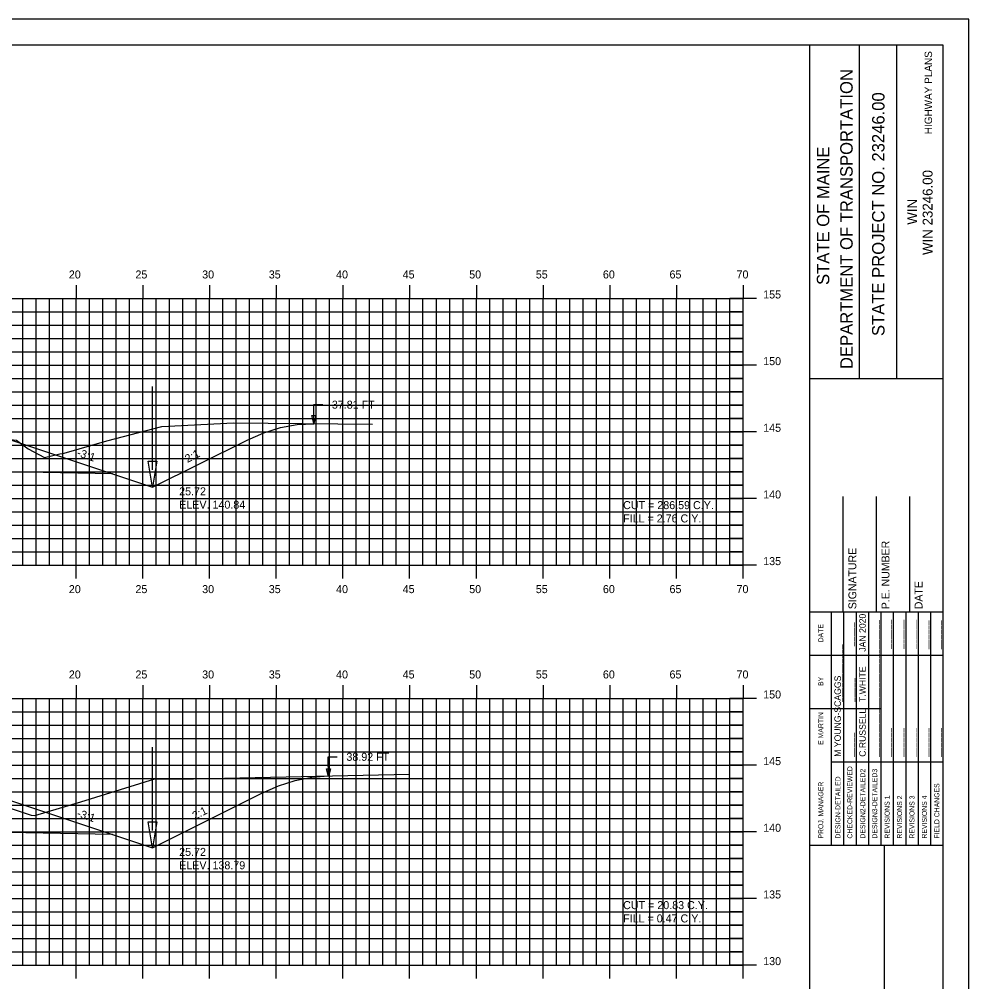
# Model space of a CAD drawing. Extents: x 1146746 to 1146916, y 608981 to 609091.
# Drawn here: x 1146845.2 to 1146916.3, y 609019.1 to 609091.3 of the extents above; entities that cross this region are included whole.
import ezdxf

# ---------------------------------------------------------------- set-up
doc = ezdxf.new("R2010")
doc.units = 0
for name, color, linetype in [('ANNOTATION', 7, 'Continuous'), ('BORDER', 7, 'Continuous'), ('D_Drainage_Ditch_Line', 7, 'Continuous'), ('D_Roadway_SlopeLines', 7, 'Continuous'), ('D_Roadway_SubGrade', 7, 'Continuous'), ('D_Text_Standard', 7, 'Continuous'), ('H_V ANNOTATION', 7, 'Continuous'), ('HIGHWAY_TITLE', 7, 'Continuous'), ('MAJOR', 7, 'Continuous'), ('MINOR', 7, 'Continuous'), ('PLOT BOUNDARY', 7, 'Continuous'), ('S_Roadway_Centerline', 7, 'Continuous')]:
    doc.layers.add(name, color=color, linetype=linetype)

msp = doc.modelspace()

# ---------------------------------------------------------------- linework, layer by layer
for points in [[(1146791.047, 609061.273), (1146792.297, 609061.185), (1146793.547, 609060.943), (1146794.797, 609060.547), (1146796.047, 609059.999), (1146803.703, 609056.171), (1146806.703, 609057.171), (1146814.427, 609059.745), (1146814.428, 609059.745), (1146818.428, 609059.905), (1146829.428, 609060.125), (1146840.428, 609059.905), (1146844.428, 609059.745), (1146852.151, 609057.171), (1146855.151, 609056.171), (1146862.242, 609059.716), (1146863.492, 609060.262), (1146864.742, 609060.648), (1146865.992, 609060.875), (1146867.242, 609060.943)], [(1146800.428, 609033.54), (1146814.428, 609032.7), (1146818.428, 609032.86), (1146829.428, 609033.08), (1146840.428, 609032.86), (1146844.428, 609032.7), (1146852.151, 609030.126), (1146855.151, 609029.126), (1146863.344, 609033.222), (1146864.594, 609033.772), (1146865.844, 609034.173), (1146867.094, 609034.424), (1146868.344, 609034.526)]]:
    msp.add_lwpolyline(points)
at = {"layer": 'BORDER'}
for p, q in [((1146904.428, 608984.335), (1146904.428, 609089.335)), ((1146908.157, 609064.332), (1146908.157, 609089.332)), ((1146910.952, 609064.332), (1146910.952, 609089.332)), ((1146904.429, 609064.329), (1146914.428, 609064.329)), ((1146906.928, 609046.838), (1146906.928, 609055.485)), ((1146909.428, 609046.838), (1146909.428, 609055.485)), ((1146911.928, 609046.838), (1146911.928, 609055.485)), ((1146904.428, 609046.838), (1146914.428, 609046.838)), ((1146904.428, 609029.338), (1146914.428, 609029.338)), ((1146910.019, 608994.338), (1146910.019, 609029.338))]:
    msp.add_line(p, q, dxfattribs=at)
msp.add_lwpolyline([(1146754.428, 608984.335), (1146914.428, 608984.335), (1146914.428, 609089.335), (1146754.428, 609089.335)], close=True, dxfattribs=at)
for points in [[(1146906.043, 609043.588), (1146906.043, 609046.838)], [(1146906.975, 609029.341), (1146906.975, 609046.838)], [(1146907.907, 609046.838), (1146907.907, 609029.341)], [(1146908.839, 609029.341), (1146908.839, 609046.838)], [(1146909.771, 609029.341), (1146909.771, 609046.838)], [(1146910.702, 609029.341), (1146910.702, 609046.838)], [(1146911.634, 609029.341), (1146911.634, 609046.838)], [(1146912.566, 609029.341), (1146912.566, 609046.838)], [(1146913.497, 609029.341), (1146913.497, 609046.838)], [(1146906.044, 609029.341), (1146906.044, 609046.132)], [(1146904.428, 609043.588), (1146914.428, 609043.588)], [(1146904.428, 609039.588), (1146906.044, 609039.588)], [(1146906.043, 609039.588), (1146909.77, 609039.588)], [(1146906.043, 609035.588), (1146914.428, 609035.588)]]:
    msp.add_lwpolyline(points, dxfattribs=at)
at = {"layer": 'D_Drainage_Ditch_Line'}
for p, q in [((1146855.151, 609057.483), (1146855.152, 609063.727)), ((1146855.151, 609030.438), (1146855.152, 609036.681))]:
    msp.add_line(p, q, dxfattribs=at)
for points in [[(1146854.823, 609058.139), (1146855.479, 609058.139), (1146855.151, 609056.171)], [(1146854.823, 609031.094), (1146855.479, 609031.094), (1146855.151, 609029.126)]]:
    msp.add_lwpolyline(points, close=True, dxfattribs=at)
at = {"layer": 'D_Roadway_SlopeLines'}
for points in [[(1146855.151, 609056.171), (1146862.242, 609059.716), (1146863.492, 609060.262), (1146864.742, 609060.648), (1146865.992, 609060.875), (1146867.242, 609060.943)], [(1146852.151, 609057.171), (1146855.151, 609056.171)], [(1146855.151, 609029.126), (1146863.344, 609033.222), (1146864.594, 609033.772), (1146865.844, 609034.173), (1146867.094, 609034.424), (1146868.344, 609034.526)], [(1146852.151, 609030.126), (1146855.151, 609029.126)]]:
    msp.add_lwpolyline(points, dxfattribs=at)
at = {"layer": 'D_Roadway_SubGrade'}
for points in [[(1146840.428, 609059.489), (1146840.428, 609059.655), (1146844.428, 609059.495), (1146844.428, 609059.745), (1146844.428, 609059.745), (1146852.151, 609057.171), (1146840.428, 609057.405)], [(1146840.428, 609032.443), (1146840.428, 609032.61), (1146844.428, 609032.45), (1146844.428, 609032.7), (1146844.428, 609032.7), (1146852.151, 609030.126), (1146840.428, 609030.36)]]:
    msp.add_lwpolyline(points, close=True, dxfattribs=at)
at = {"layer": 'D_Text_Standard'}
for points in [[(1146867.242, 609060.966), (1146867.238, 609062.37), (1146867.918, 609062.37)], [(1146868.344, 609034.472), (1146868.327, 609035.958), (1146869.007, 609035.958)]]:
    msp.add_lwpolyline(points, dxfattribs=at)
for points in [[(1146867.242, 609060.966), (1146867.095, 609061.548), (1146867.386, 609061.549)], [(1146868.344, 609034.472), (1146868.192, 609035.053), (1146868.483, 609035.056)]]:
    msp.add_lwpolyline(points, close=True, dxfattribs=at)
at = {"layer": 'MAJOR'}
for p, q in [((1146849.428, 609071.337), (1146849.428, 609070.335)), ((1146854.428, 609071.337), (1146854.428, 609070.335)), ((1146859.428, 609071.337), (1146859.428, 609070.335)), ((1146864.428, 609071.337), (1146864.428, 609070.335)), ((1146869.428, 609071.337), (1146869.428, 609070.335)), ((1146874.428, 609071.337), (1146874.428, 609070.335)), ((1146879.428, 609071.337), (1146879.428, 609070.335)), ((1146884.428, 609071.337), (1146884.428, 609070.335)), ((1146889.428, 609071.337), (1146889.428, 609070.335)), ((1146894.428, 609071.337), (1146894.428, 609070.335)), ((1146899.428, 609071.337), (1146899.428, 609070.335)), ((1146759.428, 609070.335), (1146899.428, 609070.335)), ((1146759.428, 609070.335), (1146899.428, 609070.335)), ((1146849.428, 609050.335), (1146849.428, 609070.335)), ((1146854.428, 609050.335), (1146854.428, 609070.335)), ((1146859.428, 609050.335), (1146859.428, 609070.335)), ((1146864.428, 609050.335), (1146864.428, 609070.335)), ((1146869.428, 609050.335), (1146869.428, 609070.335)), ((1146874.428, 609050.335), (1146874.428, 609070.335)), ((1146879.428, 609050.335), (1146879.428, 609070.335)), ((1146884.428, 609050.335), (1146884.428, 609070.335)), ((1146889.428, 609050.335), (1146889.428, 609070.335)), ((1146894.428, 609050.335), (1146894.428, 609070.335)), ((1146900.43, 609070.335), (1146898.426, 609070.335)), ((1146899.428, 609050.335), (1146899.428, 609070.335)), ((1146899.428, 609050.335), (1146899.428, 609070.335)), ((1146759.428, 609065.335), (1146899.428, 609065.335)), ((1146900.43, 609065.335), (1146898.426, 609065.335)), ((1146759.428, 609060.335), (1146899.428, 609060.335)), ((1146900.43, 609060.335), (1146898.426, 609060.335)), ((1146759.428, 609055.335), (1146899.428, 609055.335)), ((1146900.43, 609055.335), (1146898.426, 609055.335)), ((1146759.428, 609050.335), (1146899.428, 609050.335)), ((1146759.428, 609050.335), (1146899.428, 609050.335)), ((1146849.428, 609049.333), (1146849.428, 609050.335)), ((1146854.428, 609049.333), (1146854.428, 609050.335)), ((1146859.428, 609049.333), (1146859.428, 609050.335)), ((1146864.428, 609049.333), (1146864.428, 609050.335)), ((1146869.428, 609049.333), (1146869.428, 609050.335)), ((1146874.428, 609049.333), (1146874.428, 609050.335)), ((1146879.428, 609049.333), (1146879.428, 609050.335)), ((1146884.428, 609049.333), (1146884.428, 609050.335)), ((1146889.428, 609049.333), (1146889.428, 609050.335)), ((1146894.428, 609049.333), (1146894.428, 609050.335)), ((1146900.43, 609050.335), (1146898.426, 609050.335)), ((1146899.428, 609049.333), (1146899.428, 609050.335)), ((1146849.428, 609041.337), (1146849.428, 609040.335)), ((1146854.428, 609041.337), (1146854.428, 609040.335)), ((1146859.428, 609041.337), (1146859.428, 609040.335)), ((1146864.428, 609041.337), (1146864.428, 609040.335)), ((1146869.428, 609041.337), (1146869.428, 609040.335)), ((1146874.428, 609041.337), (1146874.428, 609040.335)), ((1146879.428, 609041.337), (1146879.428, 609040.335)), ((1146884.428, 609041.337), (1146884.428, 609040.335)), ((1146889.428, 609041.337), (1146889.428, 609040.335)), ((1146894.428, 609041.337), (1146894.428, 609040.335)), ((1146899.428, 609041.337), (1146899.428, 609040.335)), ((1146759.428, 609040.335), (1146899.428, 609040.335)), ((1146759.428, 609040.335), (1146899.428, 609040.335)), ((1146849.428, 609020.335), (1146849.428, 609040.335)), ((1146854.428, 609020.335), (1146854.428, 609040.335)), ((1146859.428, 609020.335), (1146859.428, 609040.335)), ((1146864.428, 609020.335), (1146864.428, 609040.335)), ((1146869.428, 609020.335), (1146869.428, 609040.335)), ((1146874.428, 609020.335), (1146874.428, 609040.335)), ((1146879.428, 609020.335), (1146879.428, 609040.335)), ((1146884.428, 609020.335), (1146884.428, 609040.335)), ((1146889.428, 609020.335), (1146889.428, 609040.335)), ((1146894.428, 609020.335), (1146894.428, 609040.335)), ((1146900.43, 609040.335), (1146898.426, 609040.335)), ((1146899.428, 609020.335), (1146899.428, 609040.335)), ((1146899.428, 609020.335), (1146899.428, 609040.335)), ((1146759.428, 609035.335), (1146899.428, 609035.335)), ((1146900.43, 609035.335), (1146898.426, 609035.335)), ((1146759.428, 609030.335), (1146899.428, 609030.335)), ((1146900.43, 609030.335), (1146898.426, 609030.335)), ((1146759.428, 609025.335), (1146899.428, 609025.335)), ((1146900.43, 609025.335), (1146898.426, 609025.335)), ((1146759.428, 609020.335), (1146899.428, 609020.335)), ((1146759.428, 609020.335), (1146899.428, 609020.335)), ((1146849.428, 609019.333), (1146849.428, 609020.335)), ((1146854.428, 609019.333), (1146854.428, 609020.335)), ((1146859.428, 609019.333), (1146859.428, 609020.335)), ((1146864.428, 609019.333), (1146864.428, 609020.335)), ((1146869.428, 609019.333), (1146869.428, 609020.335)), ((1146874.428, 609019.333), (1146874.428, 609020.335)), ((1146879.428, 609019.333), (1146879.428, 609020.335)), ((1146884.428, 609019.333), (1146884.428, 609020.335)), ((1146889.428, 609019.333), (1146889.428, 609020.335)), ((1146894.428, 609019.333), (1146894.428, 609020.335)), ((1146900.43, 609020.335), (1146898.426, 609020.335)), ((1146899.428, 609019.333), (1146899.428, 609020.335))]:
    msp.add_line(p, q, dxfattribs=at)
at = {"layer": 'MINOR'}
for p, q in [((1146845.428, 609050.335), (1146845.428, 609070.335)), ((1146846.428, 609050.335), (1146846.428, 609070.335)), ((1146847.428, 609050.335), (1146847.428, 609070.335)), ((1146848.428, 609050.335), (1146848.428, 609070.335)), ((1146850.428, 609050.335), (1146850.428, 609070.335)), ((1146851.428, 609050.335), (1146851.428, 609070.335)), ((1146852.428, 609050.335), (1146852.428, 609070.335)), ((1146853.428, 609050.335), (1146853.428, 609070.335)), ((1146855.428, 609050.335), (1146855.428, 609070.335)), ((1146856.428, 609050.335), (1146856.428, 609070.335)), ((1146857.428, 609050.335), (1146857.428, 609070.335)), ((1146858.428, 609050.335), (1146858.428, 609070.335)), ((1146860.428, 609050.335), (1146860.428, 609070.335)), ((1146861.428, 609050.335), (1146861.428, 609070.335)), ((1146862.428, 609050.335), (1146862.428, 609070.335)), ((1146863.428, 609050.335), (1146863.428, 609070.335)), ((1146865.428, 609050.335), (1146865.428, 609070.335)), ((1146866.428, 609050.335), (1146866.428, 609070.335)), ((1146867.428, 609050.335), (1146867.428, 609070.335)), ((1146868.428, 609050.335), (1146868.428, 609070.335)), ((1146870.428, 609050.335), (1146870.428, 609070.335)), ((1146871.428, 609050.335), (1146871.428, 609070.335)), ((1146872.428, 609050.335), (1146872.428, 609070.335)), ((1146873.428, 609050.335), (1146873.428, 609070.335)), ((1146875.428, 609050.335), (1146875.428, 609070.335)), ((1146876.428, 609050.335), (1146876.428, 609070.335)), ((1146877.428, 609050.335), (1146877.428, 609070.335)), ((1146878.428, 609050.335), (1146878.428, 609070.335)), ((1146880.428, 609050.335), (1146880.428, 609070.335)), ((1146881.428, 609050.335), (1146881.428, 609070.335)), ((1146882.428, 609050.335), (1146882.428, 609070.335)), ((1146883.428, 609050.335), (1146883.428, 609070.335)), ((1146885.428, 609050.335), (1146885.428, 609070.335)), ((1146886.428, 609050.335), (1146886.428, 609070.335)), ((1146887.428, 609050.335), (1146887.428, 609070.335)), ((1146888.428, 609050.335), (1146888.428, 609070.335)), ((1146890.428, 609050.335), (1146890.428, 609070.335)), ((1146891.428, 609050.335), (1146891.428, 609070.335)), ((1146892.428, 609050.335), (1146892.428, 609070.335)), ((1146893.428, 609050.335), (1146893.428, 609070.335)), ((1146895.428, 609050.335), (1146895.428, 609070.335)), ((1146896.428, 609050.335), (1146896.428, 609070.335)), ((1146897.428, 609050.335), (1146897.428, 609070.335)), ((1146898.428, 609050.335), (1146898.428, 609070.335)), ((1146759.428, 609069.335), (1146899.428, 609069.335)), ((1146899.428, 609069.335), (1146898.426, 609069.335)), ((1146759.428, 609068.335), (1146899.428, 609068.335)), ((1146899.428, 609068.335), (1146898.426, 609068.335)), ((1146759.428, 609067.335), (1146899.428, 609067.335)), ((1146899.428, 609067.335), (1146898.426, 609067.335)), ((1146759.428, 609066.335), (1146899.428, 609066.335)), ((1146899.428, 609066.335), (1146898.426, 609066.335)), ((1146759.428, 609064.335), (1146899.428, 609064.335)), ((1146899.428, 609064.335), (1146898.426, 609064.335)), ((1146759.428, 609063.335), (1146899.428, 609063.335)), ((1146899.428, 609063.335), (1146898.426, 609063.335)), ((1146759.428, 609062.335), (1146899.428, 609062.335)), ((1146899.428, 609062.335), (1146898.426, 609062.335)), ((1146759.428, 609061.335), (1146899.428, 609061.335)), ((1146899.428, 609061.335), (1146898.426, 609061.335)), ((1146759.428, 609059.335), (1146899.428, 609059.335)), ((1146899.428, 609059.335), (1146898.426, 609059.335)), ((1146759.428, 609058.335), (1146899.428, 609058.335)), ((1146899.428, 609058.335), (1146898.426, 609058.335)), ((1146759.428, 609057.335), (1146899.428, 609057.335)), ((1146899.428, 609057.335), (1146898.426, 609057.335)), ((1146759.428, 609056.335), (1146899.428, 609056.335)), ((1146899.428, 609056.335), (1146898.426, 609056.335)), ((1146759.428, 609054.335), (1146899.428, 609054.335)), ((1146899.428, 609054.335), (1146898.426, 609054.335)), ((1146759.428, 609053.335), (1146899.428, 609053.335)), ((1146899.428, 609053.335), (1146898.426, 609053.335)), ((1146759.428, 609052.335), (1146899.428, 609052.335)), ((1146899.428, 609052.335), (1146898.426, 609052.335)), ((1146759.428, 609051.335), (1146899.428, 609051.335)), ((1146899.428, 609051.335), (1146898.426, 609051.335)), ((1146845.428, 609020.335), (1146845.428, 609040.335)), ((1146846.428, 609020.335), (1146846.428, 609040.335)), ((1146847.428, 609020.335), (1146847.428, 609040.335)), ((1146848.428, 609020.335), (1146848.428, 609040.335)), ((1146850.428, 609020.335), (1146850.428, 609040.335)), ((1146851.428, 609020.335), (1146851.428, 609040.335)), ((1146852.428, 609020.335), (1146852.428, 609040.335)), ((1146853.428, 609020.335), (1146853.428, 609040.335)), ((1146855.428, 609020.335), (1146855.428, 609040.335)), ((1146856.428, 609020.335), (1146856.428, 609040.335)), ((1146857.428, 609020.335), (1146857.428, 609040.335)), ((1146858.428, 609020.335), (1146858.428, 609040.335)), ((1146860.428, 609020.335), (1146860.428, 609040.335)), ((1146861.428, 609020.335), (1146861.428, 609040.335)), ((1146862.428, 609020.335), (1146862.428, 609040.335)), ((1146863.428, 609020.335), (1146863.428, 609040.335)), ((1146865.428, 609020.335), (1146865.428, 609040.335)), ((1146866.428, 609020.335), (1146866.428, 609040.335)), ((1146867.428, 609020.335), (1146867.428, 609040.335)), ((1146868.428, 609020.335), (1146868.428, 609040.335)), ((1146870.428, 609020.335), (1146870.428, 609040.335)), ((1146871.428, 609020.335), (1146871.428, 609040.335)), ((1146872.428, 609020.335), (1146872.428, 609040.335)), ((1146873.428, 609020.335), (1146873.428, 609040.335)), ((1146875.428, 609020.335), (1146875.428, 609040.335)), ((1146876.428, 609020.335), (1146876.428, 609040.335)), ((1146877.428, 609020.335), (1146877.428, 609040.335)), ((1146878.428, 609020.335), (1146878.428, 609040.335)), ((1146880.428, 609020.335), (1146880.428, 609040.335)), ((1146881.428, 609020.335), (1146881.428, 609040.335)), ((1146882.428, 609020.335), (1146882.428, 609040.335)), ((1146883.428, 609020.335), (1146883.428, 609040.335)), ((1146885.428, 609020.335), (1146885.428, 609040.335)), ((1146886.428, 609020.335), (1146886.428, 609040.335)), ((1146887.428, 609020.335), (1146887.428, 609040.335)), ((1146888.428, 609020.335), (1146888.428, 609040.335)), ((1146890.428, 609020.335), (1146890.428, 609040.335)), ((1146891.428, 609020.335), (1146891.428, 609040.335)), ((1146892.428, 609020.335), (1146892.428, 609040.335)), ((1146893.428, 609020.335), (1146893.428, 609040.335)), ((1146895.428, 609020.335), (1146895.428, 609040.335)), ((1146896.428, 609020.335), (1146896.428, 609040.335)), ((1146897.428, 609020.335), (1146897.428, 609040.335)), ((1146898.428, 609020.335), (1146898.428, 609040.335)), ((1146759.428, 609039.335), (1146899.428, 609039.335)), ((1146899.428, 609039.335), (1146898.426, 609039.335)), ((1146759.428, 609038.335), (1146899.428, 609038.335)), ((1146899.428, 609038.335), (1146898.426, 609038.335)), ((1146759.428, 609037.335), (1146899.428, 609037.335)), ((1146899.428, 609037.335), (1146898.426, 609037.335)), ((1146759.428, 609036.335), (1146899.428, 609036.335)), ((1146899.428, 609036.335), (1146898.426, 609036.335)), ((1146759.428, 609034.335), (1146899.428, 609034.335)), ((1146899.428, 609034.335), (1146898.426, 609034.335)), ((1146759.428, 609033.335), (1146899.428, 609033.335)), ((1146899.428, 609033.335), (1146898.426, 609033.335)), ((1146759.428, 609032.335), (1146899.428, 609032.335)), ((1146899.428, 609032.335), (1146898.426, 609032.335)), ((1146759.428, 609031.335), (1146899.428, 609031.335)), ((1146899.428, 609031.335), (1146898.426, 609031.335)), ((1146759.428, 609029.335), (1146899.428, 609029.335)), ((1146899.428, 609029.335), (1146898.426, 609029.335)), ((1146759.428, 609028.335), (1146899.428, 609028.335)), ((1146899.428, 609028.335), (1146898.426, 609028.335)), ((1146759.428, 609027.335), (1146899.428, 609027.335)), ((1146899.428, 609027.335), (1146898.426, 609027.335)), ((1146759.428, 609026.335), (1146899.428, 609026.335)), ((1146899.428, 609026.335), (1146898.426, 609026.335)), ((1146759.428, 609024.335), (1146899.428, 609024.335)), ((1146899.428, 609024.335), (1146898.426, 609024.335)), ((1146759.428, 609023.335), (1146899.428, 609023.335)), ((1146899.428, 609023.335), (1146898.426, 609023.335)), ((1146759.428, 609022.335), (1146899.428, 609022.335)), ((1146899.428, 609022.335), (1146898.426, 609022.335)), ((1146759.428, 609021.335), (1146899.428, 609021.335)), ((1146899.428, 609021.335), (1146898.426, 609021.335))]:
    msp.add_line(p, q, dxfattribs=at)
at = {"layer": 'PLOT BOUNDARY'}
msp.add_lwpolyline([(1146746.335, 608981.276), (1146916.335, 608981.276), (1146916.335, 609091.276), (1146746.335, 609091.276)], close=True, dxfattribs=at)
at = {"layer": 'S_Roadway_Centerline'}
for points in [[(1146779.336, 609061.362), (1146783.547, 609061.347), (1146805.256, 609061.134), (1146809.082, 609059.861), (1146811.069, 609059.254), (1146812.495, 609059.513), (1146815.447, 609060.131), (1146817.252, 609060.222), (1146817.72, 609060.231), (1146827.705, 609060.397), (1146828.534, 609060.409), (1146838.673, 609060.265), (1146839.449, 609060.245), (1146840.103, 609060.192), (1146841.398, 609060.074), (1146844.953, 609059.719), (1146845.827, 609059.059), (1146847.055, 609058.398), (1146848.196, 609058.671), (1146848.525, 609058.74), (1146851.732, 609059.665), (1146855.862, 609060.73), (1146861.215, 609060.999), (1146871.652, 609060.902)], [(1146843.479, 609032.432), (1146846.056, 609031.591), (1146846.33, 609031.55), (1146849.769, 609032.589), (1146855.329, 609034.311), (1146858.231, 609034.309), (1146874.41, 609034.655)]]:
    msp.add_lwpolyline(points, dxfattribs=at)

# ---------------------------------------------------------------- texts
at = {"layer": 'ANNOTATION'}
for s, rotation, p in [('-3:1', 341.56521, (1146849.439, 609058.529)), ('2:1', 26.56505, (1146857.769, 609057.998)), ('2:1', 26.56505, (1146858.32, 609031.228)), ('-3:1', 341.56521, (1146849.439, 609031.484))]:
    msp.add_text(s, height=0.6, rotation=rotation, dxfattribs=at).set_placement(p)
at = {"layer": 'BORDER'}
for s, height, p in [('DEPARTMENT OF TRANSPORTATION', 0.93176, (1146907.635, 609065.041)), ('STATE PROJECT NO. 23246.00', 0.93176, (1146910.02, 609067.517)), ('STATE OF MAINE', 0.93176, (1146905.883, 609071.347)), ('WIN 23246.00', 0.74527, (1146913.624, 609073.596)), ('WIN', 0.7453, (1146912.465, 609075.865)), ('SIGNATURE', 0.5906, (1146907.908, 609047.03)), ('P.E. NUMBER', 0.59055, (1146910.389, 609047.03)), ('DATE', 0.5906, (1146912.869, 609047.03)), ('JAN 2020', 0.4845, (1146908.614, 609043.843)), ('DATE', 0.3714, (1146905.432, 609044.544)), ('_____', 0.4845, (1146907.645, 609044.243)), ('______', 0.4845, (1146909.509, 609044.063)), ('______', 0.4845, (1146910.44, 609044.065)), ('______', 0.4845, (1146911.372, 609044.067)), ('______', 0.4845, (1146912.304, 609044.067)), ('______', 0.4845, (1146913.235, 609044.036)), ('______', 0.4845, (1146914.167, 609044.036)), ('____________', 0.48455, (1146906.751, 609040.073)), ('____________', 0.48455, (1146909.509, 609040.073)), ('T.WHITE', 0.4845, (1146908.614, 609040.073)), ('BY', 0.3714, (1146905.432, 609041.273)), ('M YOUNG-SCAGGS', 0.48455, (1146906.751, 609035.961)), ('_____', 0.4845, (1146907.683, 609040.073)), ('____________', 0.48455, (1146909.509, 609035.961)), ('C.RUSSELL', 0.4845, (1146908.614, 609035.961)), ('E MARTIN', 0.3727, (1146905.432, 609036.855)), ('_____', 0.4845, (1146907.645, 609035.961)), ('______', 0.4845, (1146910.44, 609035.961)), ('______', 0.4845, (1146911.372, 609035.961)), ('______', 0.4845, (1146912.304, 609035.961)), ('______', 0.4845, (1146913.235, 609035.961)), ('______', 0.4845, (1146914.167, 609035.961)), ('CHECKED-REVIEWED', 0.37275, (1146907.609, 609029.826)), ('DESIGN2-DETAILED2', 0.37275, (1146908.578, 609029.826)), ('DESIGN3-DETAILED3', 0.37275, (1146909.472, 609029.826)), ('DESIGN-DETAILED', 0.37275, (1146906.715, 609029.826)), ('PROJ. MANAGER', 0.37275, (1146905.432, 609029.826)), ('FIELD CHANGES', 0.37275, (1146914.131, 609029.826)), ('REVISIONS 1', 0.37275, (1146910.404, 609029.826)), ('REVISIONS 2', 0.37275, (1146911.336, 609029.826)), ('REVISIONS 3', 0.37275, (1146912.267, 609029.826)), ('REVISIONS 4', 0.37275, (1146913.199, 609029.826))]:
    msp.add_text(s, height=height, rotation=90, dxfattribs=at).set_placement(p)
at = {"layer": 'D_Text_Standard'}
for s, p in [('37.81 FT', (1146868.598, 609062.07)), ('25.72', (1146857.151, 609055.571)), ('ELEV. 140.84', (1146857.151, 609054.569)), ('CUT = 286.59 C.Y.', (1146890.428, 609054.535)), ('FILL = 2.76 C.Y.', (1146890.428, 609053.539)), ('38.92 FT', (1146869.687, 609035.658)), ('25.72', (1146857.151, 609028.526)), ('ELEV. 138.79', (1146857.151, 609027.524)), ('CUT = 20.83 C.Y.', (1146890.428, 609024.535)), ('FILL = 0.47 C.Y.', (1146890.428, 609023.539))]:
    msp.add_text(s, height=0.6, dxfattribs=at).set_placement(p)
at = {"layer": 'H_V ANNOTATION'}
for s, p in [('20', (1146848.882, 609071.835)), ('25', (1146853.874, 609071.835)), ('30', (1146858.876, 609071.835)), ('35', (1146863.868, 609071.835)), ('40', (1146868.914, 609071.835)), ('45', (1146873.906, 609071.835)), ('50', (1146878.892, 609071.835)), ('55', (1146883.884, 609071.835)), ('60', (1146888.914, 609071.835)), ('65', (1146893.906, 609071.835)), ('70', (1146898.93, 609071.835)), ('155', (1146900.928, 609070.335)), ('150', (1146900.928, 609065.335)), ('145', (1146900.928, 609060.335)), ('140', (1146900.928, 609055.335)), ('135', (1146900.928, 609050.335)), ('20', (1146848.882, 609048.235)), ('25', (1146853.874, 609048.235)), ('30', (1146858.876, 609048.235)), ('35', (1146863.868, 609048.235)), ('40', (1146868.914, 609048.235)), ('45', (1146873.906, 609048.235)), ('50', (1146878.892, 609048.235)), ('55', (1146883.884, 609048.235)), ('60', (1146888.914, 609048.235)), ('65', (1146893.906, 609048.235)), ('70', (1146898.93, 609048.235)), ('20', (1146848.882, 609041.835)), ('25', (1146853.874, 609041.835)), ('30', (1146858.876, 609041.835)), ('35', (1146863.868, 609041.835)), ('40', (1146868.914, 609041.835)), ('45', (1146873.906, 609041.835)), ('50', (1146878.892, 609041.835)), ('55', (1146883.884, 609041.835)), ('60', (1146888.914, 609041.835)), ('65', (1146893.906, 609041.835)), ('70', (1146898.93, 609041.835)), ('150', (1146900.928, 609040.335)), ('145', (1146900.928, 609035.335)), ('140', (1146900.928, 609030.335)), ('135', (1146900.928, 609025.335)), ('130', (1146900.928, 609020.335))]:
    msp.add_text(s, height=0.6, dxfattribs=at).set_placement(p)
at = {"layer": 'HIGHWAY_TITLE'}
msp.add_text('HIGHWAY PLANS', height=0.55901, rotation=90, dxfattribs=at).set_placement((1146913.586, 609082.65))

doc.saveas('drawing.dxf')
